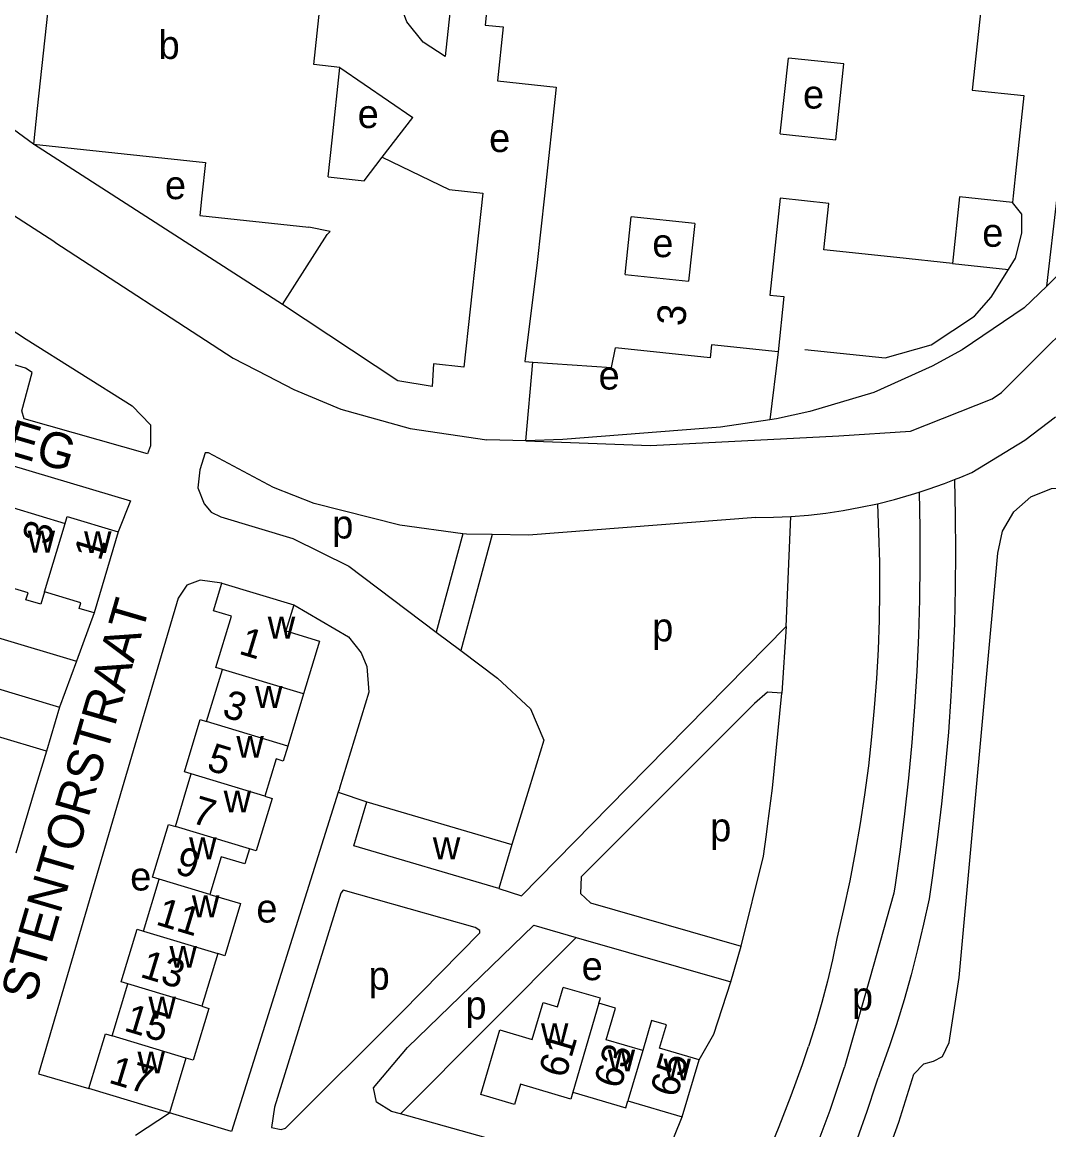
# Model space of a CAD drawing. Extents: x 161773 to 163836, y 384796 to 386521.
# Drawn here: x 162783.7 to 162928.2, y 386118.6 to 386274.5 of the extents above; entities that cross this region are included whole.
import ezdxf

# ---------------------------------------------------------------- set-up
doc = ezdxf.new("R2010")
doc.units = 0
for name, color, linetype in [('BLT_Basislijn', 7, 'Continuous'), ('BLT_Bebouwing', 7, 'Continuous'), ('BLT_Centroide', 7, 'Continuous'), ('BLT_Huisnummer', 7, 'Continuous'), ('BLT_Huisnummer_ tussenligend', 7, 'Continuous'), ('BLT_Onderverdeling_panden', 7, 'Continuous'), ('BLT_Straatnaam', 7, 'Continuous'), ('BLT_Vlakafsluiter', 7, 'Continuous')]:
    doc.layers.add(name, color=color, linetype=linetype)

msp = doc.modelspace()

# ---------------------------------------------------------------- linework, layer by layer
at = {"layer": 'BLT_Basislijn'}
for p, q in [((162927.93, 386237.3), (162959.8, 386268.77)), ((162828.43, 386268.1), (162838.7, 386261.03)), ((162834.38, 386255.45), (162838.7, 386261.03)), ((162820.34, 386234.71), (162785.3, 386257.31)), ((162788.3, 386243.5), (162776, 386251.43)), ((162914.66, 386240.49), (162922.55, 386239.64)), ((162890.1, 386228.05), (162888.94, 386218.51)), ((162854.58, 386215.54), (162855.59, 386226.63)), ((162854.58, 386215.54), (162849.12, 386215.7)), ((162722.16, 386205.26), (162791.33, 386184.56)), ((162891.23, 386189.43), (162891.91, 386204.9)), ((162845.74, 386202.48), (162842, 386188.61)), ((162849.84, 386202.35), (162845.45, 386186.02)), ((162793.81, 386191.35), (162791.33, 386184.56)), ((162891.23, 386189.43), (162890.63, 386180.03)), ((162842, 386188.61), (162845.45, 386186.02)), ((162791.33, 386184.56), (162788.97, 386178.08)), ((162828.2, 386166.09), (162832.2, 386164.76)), ((162888.47, 386160.14), (162888.63, 386161.32)), ((162836.94, 386120.84), (162861.7, 386145.67)), ((162861.7, 386145.67), (162883.47, 386139.44)), ((162883.47, 386139.44), (162884.9, 386144.44)), ((162799.65, 386117.82), (162804.46, 386120.98)), ((162872.7, 386110.89), (162836.94, 386120.84)), ((162872.7, 386110.89), (162876.61, 386120.4))]:
    msp.add_line(p, q, dxfattribs=at)
for points in [[(162898.65, 386216.26), (162908.75, 386216.9), (162920.26, 386221.46), (162921.56, 386222.36), (162995.46, 386296.02), (163013.45, 386315.51)], [(162785.3, 386257.31), (162775.02, 386264.78), (162783.9, 386277.62), (162767.85, 386288.49), (162782.67, 386311.47), (162784.47, 386312.01)], [(162927.93, 386237.3), (162929.39, 386249.77), (162938.43, 386249.36), (162941.67, 386274.1)], [(162730, 386232.36), (162734.32, 386247.55), (162737.19, 386256.05), (162739.7, 386257.79), (162741.55, 386257.8), (162784.24, 386229.83), (162799.19, 386220.49), (162801.74, 386217.79), (162801.74, 386214.83), (162801.33, 386213.72)], [(162922.55, 386239.64), (162923.55, 386241.25), (162924.44, 386244.78), (162924.41, 386247.42), (162923.11, 386249.1)], [(162788.3, 386243.5), (162813.4, 386227.17), (162818.22, 386224.67)], [(162893.89, 386228.38), (162905.2, 386227.21), (162911.68, 386229.03), (162917.74, 386233.09), (162920.12, 386235.74), (162922.55, 386239.64)], [(162801.33, 386213.72), (162783.98, 386218.65), (162783.66, 386219.76), (162785.09, 386225.17), (162784.15, 386225.77), (162744.51, 386237.83), (162742.98, 386237.68), (162741.42, 386233.56), (162738.79, 386231.51), (162734.87, 386230.99), (162730, 386232.36)], [(162927.93, 386237.3), (162924.76, 386234.24), (162916.01, 386228.36), (162911.78, 386226.03), (162903.6, 386222.35), (162894.58, 386219.65)], [(162728.73, 386228.04), (162798.94, 386207.09), (162797.22, 386202.74)], [(162818.22, 386224.67), (162821.95, 386222.75), (162828.54, 386219.99), (162838.31, 386217.3), (162849.12, 386215.7)], [(162894.58, 386219.65), (162889.91, 386218.66), (162888.94, 386218.51)], [(162917.4, 386211.11), (162924.83, 386215.64), (162929.18, 386218.91)], [(162888.94, 386218.51), (162882.02, 386217.48), (162859.81, 386215.72), (162854.58, 386215.54)], [(162854.58, 386215.54), (162872.17, 386214.9), (162898.65, 386216.26)], [(162845.74, 386202.48), (162836.88, 386203.69), (162824.79, 386206.74), (162819.06, 386208.97), (162809.92, 386213.87), (162809.46, 386213.84), (162808.69, 386211.44), (162808.41, 386208.94), (162809.32, 386206.7), (162810.3, 386205.5), (162811.65, 386204.83), (162821.79, 386201.78), (162829.66, 386197.9), (162842, 386188.61)], [(162914.93, 386210.09), (162915.85, 386210.45), (162917.4, 386211.11)], [(162909.98, 386208.33), (162911.23, 386208.73), (162913.55, 386209.55), (162914.93, 386210.09)], [(162914.93, 386210.09), (162915.05, 386205.01), (162915.09, 386199.93), (162915.05, 386194.85), (162914.93, 386189.77), (162914.73, 386184.7), (162914.45, 386179.63), (162914.08, 386174.56), (162913.64, 386169.51), (162913.12, 386164.45), (162912.52, 386159.41), (162911.85, 386154.38), (162911.36, 386151.12)], [(162891.41, 386084.07), (162900.49, 386101.33), (162907.09, 386119.69), (162909.24, 386126.41), (162910.61, 386127.86), (162911.99, 386128.24), (162913.24, 386128.93), (162914.19, 386130.86), (162915.62, 386140.02), (162921.03, 386199.73), (162921.72, 386202.82), (162923.32, 386205.55), (162925.68, 386207.66), (162928.62, 386208.84), (162931.78, 386208.87), (162934.86, 386208.12), (162937.62, 386206.58), (162939.89, 386204.37), (162994.17, 386149.84)], [(162904.09, 386206.7), (162906.5, 386207.3), (162908.88, 386207.98), (162909.98, 386208.33)], [(162909.98, 386208.33), (162910.07, 386203.28), (162910.08, 386198.24), (162910.02, 386193.2), (162909.87, 386188.17), (162909.64, 386183.13), (162909.33, 386178.1), (162908.95, 386173.08), (162908.48, 386168.06), (162907.93, 386163.05), (162907.31, 386158.06), (162906.6, 386153.07), (162906.42, 386151.88)], [(162904.09, 386206.7), (162904.27, 386202.6), (162904.37, 386198.49), (162904.39, 386194.39), (162904.33, 386190.29), (162904.18, 386186.18), (162903.96, 386182.08), (162903.66, 386177.99), (162903.28, 386173.9), (162902.83, 386169.82), (162902.29, 386165.75), (162901.67, 386161.7), (162900.97, 386157.65), (162900.2, 386153.62), (162899.34, 386149.6), (162898.39, 386145.52)], [(162886.98, 386204.74), (162854.96, 386202.26), (162849.84, 386202.35)], [(162886.98, 386204.74), (162889.45, 386204.78), (162891.91, 386204.9)], [(162849.84, 386202.35), (162846.24, 386202.42), (162845.74, 386202.48)], [(162811.79, 386195.53), (162808.75, 386195.96), (162806.9, 386195.25), (162805.65, 386193.4), (162797.78, 386166.67), (162785.99, 386126.45), (162793.09, 386124.42)], [(162821.93, 386192.46), (162829.64, 386187.97), (162831.41, 386185.71), (162832.2, 386183.8), (162832.52, 386180.2), (162828.39, 386166.67), (162828.31, 386166.43), (162828.2, 386166.09)], [(162850.82, 386152.54), (162853.99, 386151.54), (162868.86, 386166.67), (162891.23, 386189.43)], [(162845.45, 386186.02), (162850.6, 386182.14), (162855.28, 386177.83), (162857.15, 386173.41), (162855.08, 386166.67), (162852.64, 386158.74)], [(162890.63, 386180.03), (162888.64, 386180.17), (162886.8, 386178.57), (162874.87, 386166.67), (162862.39, 386154.21), (162862.28, 386151.87), (162863.71, 386150.53), (162884.9, 386144.44)], [(162888.63, 386161.32), (162889.34, 386166.67), (162890.63, 386180.03)], [(162787.11, 386171.88), (162785.54, 386166.67), (162782.8, 386157.53)], [(162828.2, 386166.09), (162813.15, 386118.36), (162804.46, 386120.98)], [(162884.9, 386144.44), (162888.06, 386157.12), (162888.47, 386160.14)], [(162837.15, 386135.16), (162848.12, 386146.3), (162848.12, 386146.62), (162847.45, 386147.04), (162828.9, 386152.3), (162828.55, 386151.88), (162819.23, 386121.77), (162818.81, 386118.94), (162820.18, 386118.65), (162820.76, 386118.82), (162837.15, 386135.16)], [(162906.42, 386151.88), (162903, 386139.73), (162899.5, 386127.61), (162899.44, 386127.43)], [(162911.36, 386151.12), (162910.6, 386147.53), (162909.76, 386143.97), (162908.84, 386140.42), (162907.85, 386136.89), (162906.78, 386133.38), (162905.8, 386130.43)], [(162836.94, 386120.84), (162835.7, 386121.18), (162833.6, 386122.49), (162833.16, 386124.49), (162837.93, 386130.16), (162855.72, 386147.38), (162861.7, 386145.67)], [(162898.39, 386145.52), (162897.77, 386142.5), (162897.07, 386139.49), (162896.29, 386136.51), (162895.43, 386133.55), (162894.5, 386130.6), (162894.4, 386130.3)], [(162878.98, 386128.44), (162881.06, 386132.07), (162883.47, 386139.44)], [(162864.52, 386069.41), (162867.05, 386073.34), (162869.51, 386077.3), (162871.9, 386081.31), (162874.23, 386085.36), (162876.48, 386089.44), (162878.66, 386093.57), (162880.77, 386097.73), (162882.82, 386101.93), (162884.79, 386106.16), (162886.68, 386110.43), (162888.5, 386114.72), (162890.25, 386119.05), (162891.93, 386123.41), (162893.53, 386127.79), (162894.4, 386130.3)], [(162905.8, 386130.43), (162905.63, 386129.9), (162904.41, 386126.45), (162904.21, 386125.92)], [(162878.32, 386081.67), (162880.42, 386085.09), (162882.44, 386088.56), (162884.39, 386092.07), (162886.27, 386095.61), (162888.08, 386099.2), (162889.82, 386102.81), (162891.49, 386106.46), (162893.08, 386110.15), (162894.61, 386113.86), (162896.05, 386117.61), (162897.42, 386121.38), (162898.72, 386125.18), (162899.44, 386127.43)], [(162883.68, 386080.82), (162885.76, 386084.31), (162887.77, 386087.84), (162889.71, 386091.41), (162891.59, 386095.02), (162893.39, 386098.66), (162895.12, 386102.34), (162896.77, 386106.05), (162898.35, 386109.79), (162899.86, 386113.57), (162901.29, 386117.37), (162902.65, 386121.2), (162903.93, 386125.06), (162904.21, 386125.92)]]:
    msp.add_lwpolyline(points, dxfattribs=at)
msp.add_lwpolyline([(162831.21, 386276.56), (162834.25, 386304.97), (162838.37, 386302.69), (162840.16, 386300), (162841.15, 386296.93), (162846.36, 386298.61), (162843.25, 386269.61), (162840.16, 386271.63), (162837.84, 386274.5), (162836.57, 386277.97)], close=True, dxfattribs=at)
at = {"layer": 'BLT_Bebouwing'}
for p, q in [((162890.42, 386258.73), (162891.56, 386269.41)), ((162899.37, 386268.57), (162891.56, 386269.41)), ((162898.22, 386257.89), (162899.37, 386268.57)), ((162890.42, 386258.73), (162898.22, 386257.89)), ((162868.57, 386238.96), (162869.44, 386247.08)), ((162878.37, 386246.12), (162869.44, 386247.08)), ((162878.37, 386246.12), (162877.5, 386238.01)), ((162914.66, 386240.49), (162906.82, 386241.33)), ((162868.57, 386238.96), (162877.5, 386238.01)), ((162782.33, 386206.16), (162789.73, 386203.93)), ((162797.22, 386202.74), (162793.81, 386191.35)), ((162811.79, 386195.53), (162821.93, 386192.46)), ((162809.66, 386176.04), (162811.88, 386183.37)), ((162787.11, 386171.88), (162758.04, 386180.59)), ((162788.97, 386178.08), (162787.11, 386171.88)), ((162832.2, 386164.76), (162852.64, 386158.74)), ((162852.64, 386158.74), (162850.82, 386152.54)), ((162800.78, 386146.55), (162802.99, 386153.88)), ((162796.35, 386131.83), (162798.56, 386139.12)), ((162876.61, 386120.4), (162878.98, 386128.44)), ((162804.46, 386120.98), (162793.09, 386124.42)), ((162868.96, 386122.65), (162876.61, 386120.4))]:
    msp.add_line(p, q, dxfattribs=at)
for points in [[(162828.43, 386268.1), (162824.74, 386268.5), (162828.95, 386307.77), (162825.59, 386308.13), (162826.55, 386317.05), (162829.31, 386316.75)], [(162829.31, 386316.75), (162828.84, 386312.31), (162836.98, 386311.44), (162836.76, 386309.33), (162855, 386307.38), (162853.44, 386292.77), (162850.89, 386293.04), (162849.39, 386279.03), (162848.86, 386274.05), (162851.4, 386273.78), (162850.59, 386266.2), (162858.85, 386265.32), (162857.21, 386250), (162856.21, 386240.65)], [(162913.93, 386312.19), (162910.37, 386278.87), (162918.85, 386277.96), (162917.45, 386264.91), (162924.72, 386264.13), (162923.65, 386254.07), (162923.21, 386250), (162923.11, 386249.1)], [(162784.47, 386312.01), (162781.85, 386288.31), (162788.54, 386287.59), (162788.53, 386287.46), (162785.83, 386262.29), (162785.3, 386257.31)], [(162826.78, 386252.68), (162827.33, 386257.83), (162828.43, 386268.1)], [(162785.3, 386257.31), (162809.5, 386254.72), (162808.99, 386250), (162808.7, 386247.26), (162824.07, 386245.61)], [(162834.38, 386255.45), (162843.83, 386250.9), (162848.56, 386250.38), (162845.87, 386225.91), (162841.59, 386226.37), (162841.42, 386223.21), (162836.56, 386223.99), (162820.34, 386234.71)], [(162826.78, 386252.68), (162831.82, 386252.14), (162834.38, 386255.45)], [(162923.11, 386249.1), (162915.67, 386249.89), (162914.66, 386240.49)], [(162906.82, 386241.33), (162896.55, 386242.43), (162897.24, 386248.96), (162890.39, 386249.7), (162888.93, 386236.06), (162890.93, 386235.85), (162890.1, 386228.05)], [(162820.34, 386234.71), (162826.65, 386244.59), (162827.04, 386244.98), (162824.07, 386245.61)], [(162856.21, 386240.65), (162854.44, 386226.71), (162855.59, 386226.63)], [(162855.59, 386226.63), (162866.67, 386225.87), (162867.2, 386228.64)], [(162890.1, 386228.05), (162880.73, 386229.05), (162880.54, 386227.22), (162867.2, 386228.64)], [(162789.73, 386203.93), (162790.02, 386204.9), (162797.22, 386202.74)], [(162786.84, 386194.3), (162786.32, 386192.54), (162784.23, 386193.17), (162784.52, 386194.14), (162779.2, 386195.74)], [(162811.88, 386183.37), (162810.97, 386183.65), (162813.15, 386190.86), (162810.61, 386191.62), (162811.79, 386195.53)], [(162793.81, 386191.35), (162791.74, 386191.97), (162791.97, 386192.76), (162786.84, 386194.3)], [(162821.93, 386192.46), (162820.82, 386188.79), (162825.54, 386187.36), (162823.29, 386179.93)], [(162758.04, 386180.59), (162759.9, 386186.79), (162788.97, 386178.08)], [(162823.29, 386179.93), (162821.08, 386172.59)], [(162807.49, 386168.67), (162806.54, 386168.96), (162808.76, 386176.32), (162809.66, 386176.04)], [(162821.08, 386172.59), (162820.44, 386170.49), (162819.46, 386170.78), (162817.88, 386165.55)], [(162805.26, 386161.28), (162806.89, 386166.67), (162807.49, 386168.67)], [(162817.88, 386165.55), (162818.87, 386165.23), (162816.64, 386157.84), (162815.68, 386158.13)], [(162850.82, 386152.54), (162830.37, 386158.57), (162832.2, 386164.76)], [(162802.99, 386153.88), (162802.06, 386154.16), (162804.3, 386161.57), (162805.26, 386161.28)], [(162815.68, 386158.13), (162815.04, 386156.02), (162811.7, 386157.03), (162810.1, 386151.73)], [(162810.1, 386151.73), (162814.42, 386150.43), (162812.21, 386143.09), (162811.22, 386143.39)], [(162798.56, 386139.12), (162797.65, 386139.4), (162799.89, 386146.81), (162800.78, 386146.55)], [(162811.22, 386143.39), (162808.98, 386135.98)], [(162861.21, 386123.9), (162860.93, 386122.93), (162853.84, 386125.02), (162853, 386122.17), (162848.25, 386123.57), (162850.93, 386132.65), (162855.49, 386131.3), (162857.02, 386136.49), (162859.07, 386135.89), (162859.87, 386138.62)], [(162864.9, 386136.41), (162865.11, 386137.11), (162859.87, 386138.62)], [(162871.05, 386129.74), (162865.91, 386131.26), (162867.22, 386135.72), (162864.9, 386136.41)], [(162808.98, 386135.98), (162809.98, 386135.67), (162809.37, 386133.65), (162807.78, 386128.38), (162806.76, 386128.69)], [(162878.98, 386128.44), (162873.43, 386130.08), (162874.4, 386133.37), (162872.3, 386133.99), (162871.05, 386129.74)], [(162793.09, 386124.42), (162795.42, 386132.11), (162796.35, 386131.83)], [(162806.75, 386128.68), (162804.46, 386120.98)], [(162861.21, 386123.9), (162868.68, 386121.69), (162868.96, 386122.65)]]:
    msp.add_lwpolyline(points, dxfattribs=at)
at = {"layer": 'BLT_Onderverdeling_panden'}
for p, q in [((162786.84, 386194.3), (162789.73, 386203.93)), ((162823.29, 386179.93), (162811.88, 386183.37)), ((162821.08, 386172.59), (162809.66, 386176.04)), ((162817.88, 386165.55), (162807.49, 386168.67)), ((162814.6, 386166.52), (162814.12, 386166.67)), ((162815.68, 386158.13), (162805.26, 386161.28)), ((162810.1, 386151.73), (162802.99, 386153.88)), ((162800.78, 386146.55), (162811.22, 386143.39)), ((162808.98, 386135.98), (162798.56, 386139.12)), ((162864.9, 386136.41), (162861.21, 386123.9)), ((162806.75, 386128.68), (162796.35, 386131.83)), ((162871.05, 386129.74), (162868.96, 386122.65))]:
    msp.add_line(p, q, dxfattribs=at)
at = {"layer": 'BLT_Vlakafsluiter'}
msp.add_lwpolyline([(162891.91, 386204.9), (162894.37, 386205.1), (162896.83, 386205.38), (162899.27, 386205.75), (162901.7, 386206.19), (162904.09, 386206.7)], dxfattribs=at)

# ---------------------------------------------------------------- texts
at = {"layer": 'BLT_Centroide'}
for s, p in [('b', (162802.9, 386269.28)), ('e', (162893.62, 386262.3)), ('e', (162830.93, 386259.56)), ('e', (162849.43, 386256.18)), ('e', (162803.79, 386249.55)), ('e', (162918.85, 386242.85)), ('e', (162872.4, 386241.39)), ('e', (162864.84, 386222.76)), ('p', (162827.35, 386201.8)), ('w', (162784.47, 386199.83)), ('w', (162792.41, 386199.75)), ('w', (162818.27, 386187.72)), ('p', (162872.39, 386187.33)), ('w', (162816.48, 386177.97)), ('w', (162813.85, 386170.94)), ('w', (162812.06, 386163.25)), ('p', (162880.55, 386159.19)), ('w', (162807.2, 386156.66)), ('w', (162841.51, 386156.66)), ('e', (162798.9, 386152.27)), ('w', (162807.59, 386148.5)), ('e', (162816.67, 386147.76)), ('w', (162804.43, 386141.41)), ('e', (162862.46, 386139.65)), ('p', (162832.47, 386138.31)), ('p', (162900.51, 386135.41)), ('w', (162801.48, 386134.25)), ('p', (162846.1, 386134.15)), ('w', (162856.73, 386130.53)), ('w', (162866.12, 386126.81)), ('w', (162799.93, 386126.53)), ('w', (162873.97, 386125.55))]:
    msp.add_text(s, height=4, dxfattribs=at).set_placement(p)
at = {"layer": 'BLT_Huisnummer'}
for s, rotation, p in [('3', 83.8869, (162876.97, 386231.59)), ('1', 73.31, (162794.73, 386198.52)), ('1', 343.1885, (162814.04, 386185.62)), ('5', 343.1879, (162809.52, 386169.27)), ('9', 343.1916, (162805.04, 386154.73)), ('13', 343.1819, (162800.15, 386140.14)), ('61', 73.5711, (162860.17, 386125.73)), ('17', 343.1945, (162795.72, 386125.26)), ('65', 73.5599, (162875.85, 386122.98))]:
    msp.add_text(s, height=4, rotation=rotation, dxfattribs=at).set_placement(p)
at = {"layer": 'BLT_Huisnummer_ tussenligend'}
for s, rotation, p in [('3', 73.31, (162787.43, 386200.72)), ('3', 343.1885, (162811.69, 386176.78)), ('7', 343.1879, (162807.35, 386161.86)), ('11', 343.1916, (162802.36, 386147.52)), ('15', 343.1819, (162797.88, 386132.6)), ('63', 73.5711, (162867.93, 386124.22))]:
    msp.add_text(s, height=4, rotation=rotation, dxfattribs=at).set_placement(p)
at = {"layer": 'BLT_Straatnaam'}
for s, height, rotation, p in [('PALAMEDESWEG', 5, 343.6112, (162735.8, 386227.14)), ('STENTORSTRAAT', 4.9999, 73.7451, (162785.4, 386136.37))]:
    msp.add_text(s, height=height, rotation=rotation, dxfattribs=at).set_placement(p)

doc.saveas('drawing.dxf')
